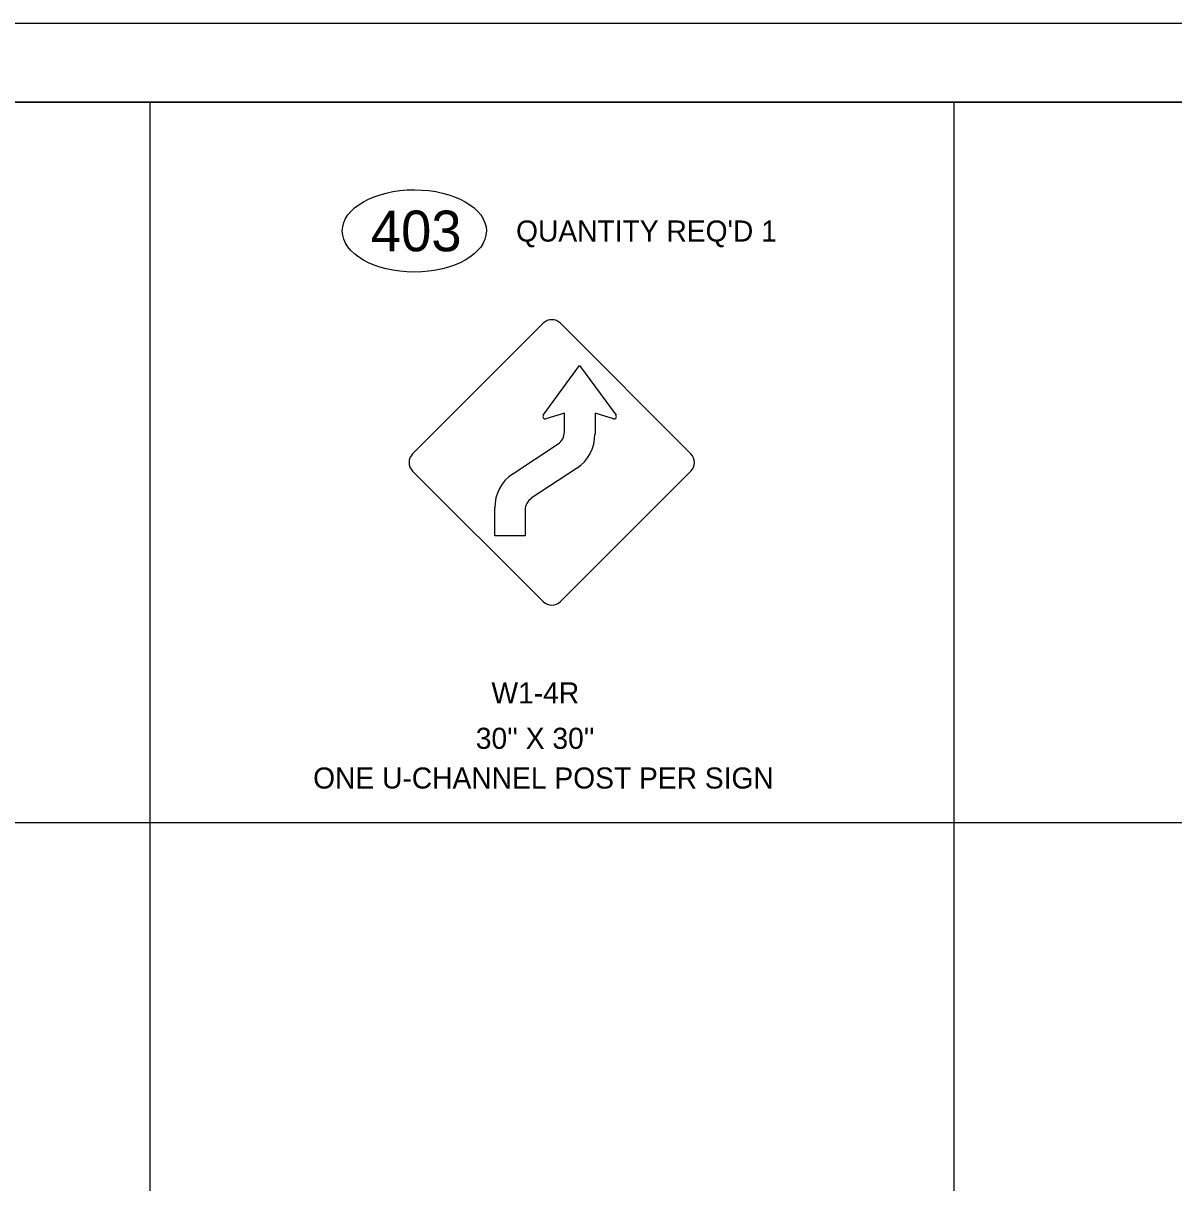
# Model space of a CAD drawing. Extents: x 1860868 to 1863318, y 1193312 to 1194425.
# Drawn here: x 1862226 to 1862772, y 1193875 to 1194425 of the extents above; entities that cross this region are included whole.
import ezdxf

# ---------------------------------------------------------------- set-up
doc = ezdxf.new("R2010")
doc.units = 0
for name, color, linetype in [('Default', 7, 'Continuous'), ('Level_1', 7, 'Continuous'), ('Old_Level_20', 7, 'Continuous'), ('Sheet Data Field CELL', 7, 'Continuous'), ('Sheet PE Seal CELL', 7, 'Continuous'), ('Sheet Plan CELL', 7, 'Continuous'), ('WZTC Sheet Plot Border', 7, 'Continuous')]:
    doc.layers.add(name, color=color, linetype=linetype)

msp = doc.modelspace()

# ---------------------------------------------------------------- linework, layer by layer
at = {"layer": 'Default'}
msp.add_line((1861523.9, 1194387.49), (1863048.9, 1194387.49), dxfattribs=at)
at = {"layer": 'Level_1'}
for p, q in [((1862286.4, 1194387.47), (1862286.38, 1193362.47)), ((1862667.65, 1194387.46), (1862667.63, 1193362.46)), ((1861523.9, 1194045.82), (1863048.9, 1194045.82))]:
    msp.add_line(p, q, dxfattribs=at)
at = {"layer": 'Old_Level_20'}
msp.add_line((1861486.4, 1194424.99), (1863186.4, 1194424.99), dxfattribs=at)
at = {"layer": 'Sheet Data Field CELL'}
msp.add_ellipse((1862411.84, 1194326.45), major_axis=(-34.16, 0.02), ratio=0.571429, dxfattribs=at)
at = {"layer": 'Sheet PE Seal CELL'}
for p, q in [((1862473.01, 1194239.05), (1862490.2, 1194262.63)), ((1862490.2, 1194262.63), (1862507.51, 1194239.05)), ((1862483, 1194240.09), (1862474.16, 1194237.32)), ((1862483, 1194231.03), (1862483, 1194240.09)), ((1862506.33, 1194237.32), (1862497.52, 1194240.09)), ((1862497.52, 1194240.09), (1862497.52, 1194230.1)), ((1862458.6, 1194211.29), (1862479.98, 1194225.46)), ((1862488.81, 1194213.84), (1862467.32, 1194199.67)), ((1862543.02, 1194212.56), (1862481.11, 1194150.65)), ((1862450.01, 1194181.9), (1862450.01, 1194195.14)), ((1862464.41, 1194194.09), (1862464.41, 1194181.9)), ((1862464.41, 1194181.9), (1862450.01, 1194181.9))]:
    msp.add_line(p, q, dxfattribs=at)
for points in [[(1862411.02, 1194220.74), (1862472.93, 1194282.65)], [(1862481.11, 1194282.65), (1862543.02, 1194220.74)], [(1862472.93, 1194150.65), (1862411.02, 1194212.56)]]:
    msp.add_lwpolyline(points, dxfattribs=at)
for centre, radius, start, end in [((1862477.02, 1194278.56), 5.78, 89.9935, 135), ((1862477.02, 1194278.56), 5.78, 44.987, 89.9935), ((1862473.93, 1194238.39), 1.1, 143.9078, 282.5697), ((1862506.56, 1194238.39), 1.1, 257.4303, 36.0922), ((1862476.34, 1194231.03), 6.64, 303.5775, 0), ((1862478.09, 1194230.05), 19.42, 303.5774, 0), ((1862415.11, 1194216.65), 5.78, 135, 225), ((1862538.94, 1194216.65), 5.78, 315, 45), ((1862469.37, 1194195.12), 19.42, 123.5774, 180), ((1862471.05, 1194194.09), 6.64, 123.5772, 180), ((1862477.02, 1194154.74), 5.78, 225, 270), ((1862477.02, 1194154.74), 5.78, 270, 315)]:
    msp.add_arc(centre, radius, start, end, dxfattribs=at)
at = {"layer": 'Sheet Plan CELL'}
msp.add_line((1863148.9, 1194387.49), (1861523.9, 1194387.49), dxfattribs=at)
at = {"layer": 'WZTC Sheet Plot Border'}
msp.add_lwpolyline([(1861486.4, 1194424.99), (1863186.4, 1194424.99), (1863186.4, 1193324.99), (1861486.4, 1193324.99)], close=True, dxfattribs=at)

# ---------------------------------------------------------------- texts
at = {"layer": 'Level_1'}
for s, p in [("QUANTITY REQ'D 1", (1862460.08, 1194321.41)), ('W1-4R', (1862448.42, 1194102.33)), ("30'' X 30''", (1862440.98, 1194080.81)), ('ONE U-CHANNEL POST PER SIGN', (1862363.84, 1194061.98))]:
    msp.add_text(s, height=10, dxfattribs=at).set_placement(p)
at = {"layer": 'Sheet Data Field CELL'}
msp.add_text('403', height=19.284, rotation=359.9659, dxfattribs=at).set_placement((1862391.21, 1194316.83))

doc.saveas('drawing.dxf')
